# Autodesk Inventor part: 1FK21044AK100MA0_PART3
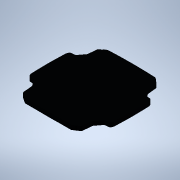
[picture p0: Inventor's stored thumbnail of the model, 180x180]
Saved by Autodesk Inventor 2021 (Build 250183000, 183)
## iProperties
Created: 2025-04
Part Number: 1FK21044AK100MA0_PART3
Material: Generic
Catalog Web Link: www.3dfindit.com
Description: -Servo synchronous motor
Document SubType Name: Modeling
Designer: psAdmin
Mass: 21.7019 g
Surface Area: 120.085 cm^2
Volume: 21.7019 cm^3
Density: 1 g/cm^3
Appearance: PSOLRGB-38-46-56
Category: PARTsolutions
Title: 1FK21044AK100MA0_PART3
Author: Cadenas PARTsolutions
Comments: Servo synchronous motor
Sending System: PARTsolutions
Preprocessor: ST-DEVELOPER v19.3
PSOL_IDENT_0: {$CADENAS_DATA/23d-libs/siemens_ag/_cat_/5e/d8/1fk21044ak100ma0.prj},213 {VTYP=3D},{NB=1FK21044AK100
PSOL_IDENT_1: MA0_PART3},{LINA=1FK21044AK100MA0_PART3},{NN=1FK21044AK100MA0_PART3},{NOPRJ=TRUE},{DATE=19.08.2025 1
PSOL_IDENT_2: 4:00:41},{GEOMDATE=30.07.2025 02:00:53},{VERSION=},{LINEID=10},{WBVAR=},{WBNUMERIC=}  {NB=1FK21044AK
PSOL_IDENT_3: 100MA0_PART3},{LINA=1FK21044AK100MA0_PART3},{KT=DUMMY},{PREVIEW=../../../_pool_/cb/72/p_d211_xx_0043
PSOL_IDENT_4: 4j.png},{DESCSHORT=SIMOTICS S-1FK2 HD, SINAMICS S210 3AC 400V-480V, 0.95 Nm, 6000 rpm},{DESCLONG=SIM
PSOL_IDENT_5: OTICS S-1FK2 HD servo motor M0=1.27 Nm; PN = 0.6 kW at nN=6000 rpm (380-480 V); PN = 0.4 kW at nN=30
PSOL_IDENT_6: 00 rpm (200-240 V); with holding brake; degree of protection IP64; cylindrical shaft D19x40mm; absol
PSOL_IDENT_7: ute encoder 22-bit + 12-bit multiturn (encoder AM22DQC); with OCC interface; plug size M17, rotatabl
PSOL_IDENT_8: e; SIMOTICS S-1FK2 servomotorfor a wide range of uses in industrial environments. SIMOTICS S‑1FK2 se
PSOL_IDENT_9: rvomotors are compact synchronous motors with a high dynamic performance that set themselves apart a
PSOL_IDENT_10: s a result of their high power density, degree of protection and overload capability. The motors are
PSOL_IDENT_11: available in two variants: as High Dynamic variant (highest dynamic performance as a result of the
PSOL_IDENT_12: low intrinsic moment of inertia for applications demanding a high dynamic performance with low moved
PSOL_IDENT_13: masses) - and as Compact variant (precise and stable closed-loop control for medium up to large mov
PSOL_IDENT_14: ed masses as a result of a medium intrinsic moment of inertia). SIMOTICSS‑1FK2 servomotors fully exp
PSOL_IDENT_15: loit their strengths in a system with the SINAMICSS210 frequency converter and simple connection usi
PSOL_IDENT_16: ng the one cable connection (OCC). Advantages include the short control and positioning times, fast
PSOL_IDENT_17: and precise correction of disturbing quantities as well as stable control with a high dynamic perfor
PSOL_IDENT_18: mance. The servo motors can be configured to address a wide range of requirements. For example with
PSOL_IDENT_19: and without holding brake, IP64 or IP65 degree of protection, singleturn or multiturn absolute encod
PSOL_IDENT_20: ers - to name just a few. Further, the servomotors are available in different shaft heights extendin
PSOL_IDENT_21: g from 20 to 100. A shaft sealing ring is available to achieve an IP65 degree of protection and for
PSOL_IDENT_22: subsequent mounting at the motor or as spare part. SIMOTICS - the optimum motor for each and every m
PSOL_IDENT_23: otion control application.},{INTNO=804766910005},{SUPPLIERALTNO=1FK2104-4AK10-0MA0},{MANUID=1FK21044
PSOL_IDENT_24: AK100MA0},{MANUNAME=Siemens},{MANUTYPEDESC=Synchronous motor 1FK2-HD 1,27 Nm},{AAU732=SIMOTICS},{AAO
PSOL_IDENT_25: 057=S-1FK2},{AAU734=SIMOTICS S-1FK2 HD servo motor M0=1.27 Nm; PN = 0.6 kW at nN=6000 rpm (380-480 V
PSOL_IDENT_26: ); PN = 0.4 kW at nN=3000 rpm (200-240 V); with holding brake; degree of protection IP64; cylindrica
PSOL_IDENT_27: l shaft D19x40mm; absolute encoder 22-bit + 12-bit multiturn (encoder AM22DQC); with OCC interface;
PSOL_IDENT_28: plug size M17, rotatable;},{AAW338=Synchronous motor 1FK2-HD 1,27 Nm},{AAO742=SIMOTICS},{AAO663=4042
PSOL_IDENT_29: 948691076},{NOCUPEROU=1},{PRICEQUANTITY=1},{QUANTITYMIN=1},{QUANTITYINT=1},{CTN=85015100},{COO=DE},{
PSOL_IDENT_30: AAO676=1FK2104-4AK10-0MA0},{AAO677=Siemens AG},{ORDERUNIT=C62},{CONTENTUNIT=C62}
NB: 1FK21044AK100MA0_PART3
NT: Servo synchronous motor
NBSYN: $MANUID._PART3
LINA: 1FK21044AK100MA0_PART3
CATALOG: SIEMENS
PREVIEW: ../../../_pool_/cb/72/p_d211_xx_00434j.png
DESCSHORT: SIMOTICS S-1FK2 HD, SINAMICS S210 3AC 400V-480V, 0.95 Nm, 6000 rpm
DESCLONG: SIMOTICS S-1FK2 HD servo motor M0=1.27 Nm; PN = 0.6 kW at nN=6000 rpm (380-480 V); PN = 0.4 kW at nN=3000 rpm (200-240 V); with holding brake; degree of protect
INTNO: 804766910005
SUPPLIERALTNO: 1FK2104-4AK10-0MA0
MANUID: 1FK21044AK100MA0
MANUNAME: Siemens
MANUTYPEDESC: Synchronous motor 1FK2-HD 1,27 Nm
AAU732: SIMOTICS
AAO057: S-1FK2
AAU734: SIMOTICS S-1FK2 HD servo motor M0=1.27 Nm; PN = 0.6 kW at nN=6000 rpm (380-480 V); PN = 0.4 kW at nN=3000 rpm (200-240 V); with holding brake; degree of protect
AAW338: Synchronous motor 1FK2-HD 1,27 Nm
AAO742: SIMOTICS
AAO663: 4042948691076.0
NOCUPEROU: 1
PRICEQUANTITY: 1
QUANTITYMIN: 1
QUANTITYINT: 1
CTN: 85015100
COO: DE
ARTICLENO: 1FK21044AK100MA0_PART3
BOMINFO: 1FK21044AK100MA0_PART3
CREATOR: CADENAS GmbH
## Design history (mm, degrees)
feature "2025_04_17_15_35_41_0874"
body "Solid1"
